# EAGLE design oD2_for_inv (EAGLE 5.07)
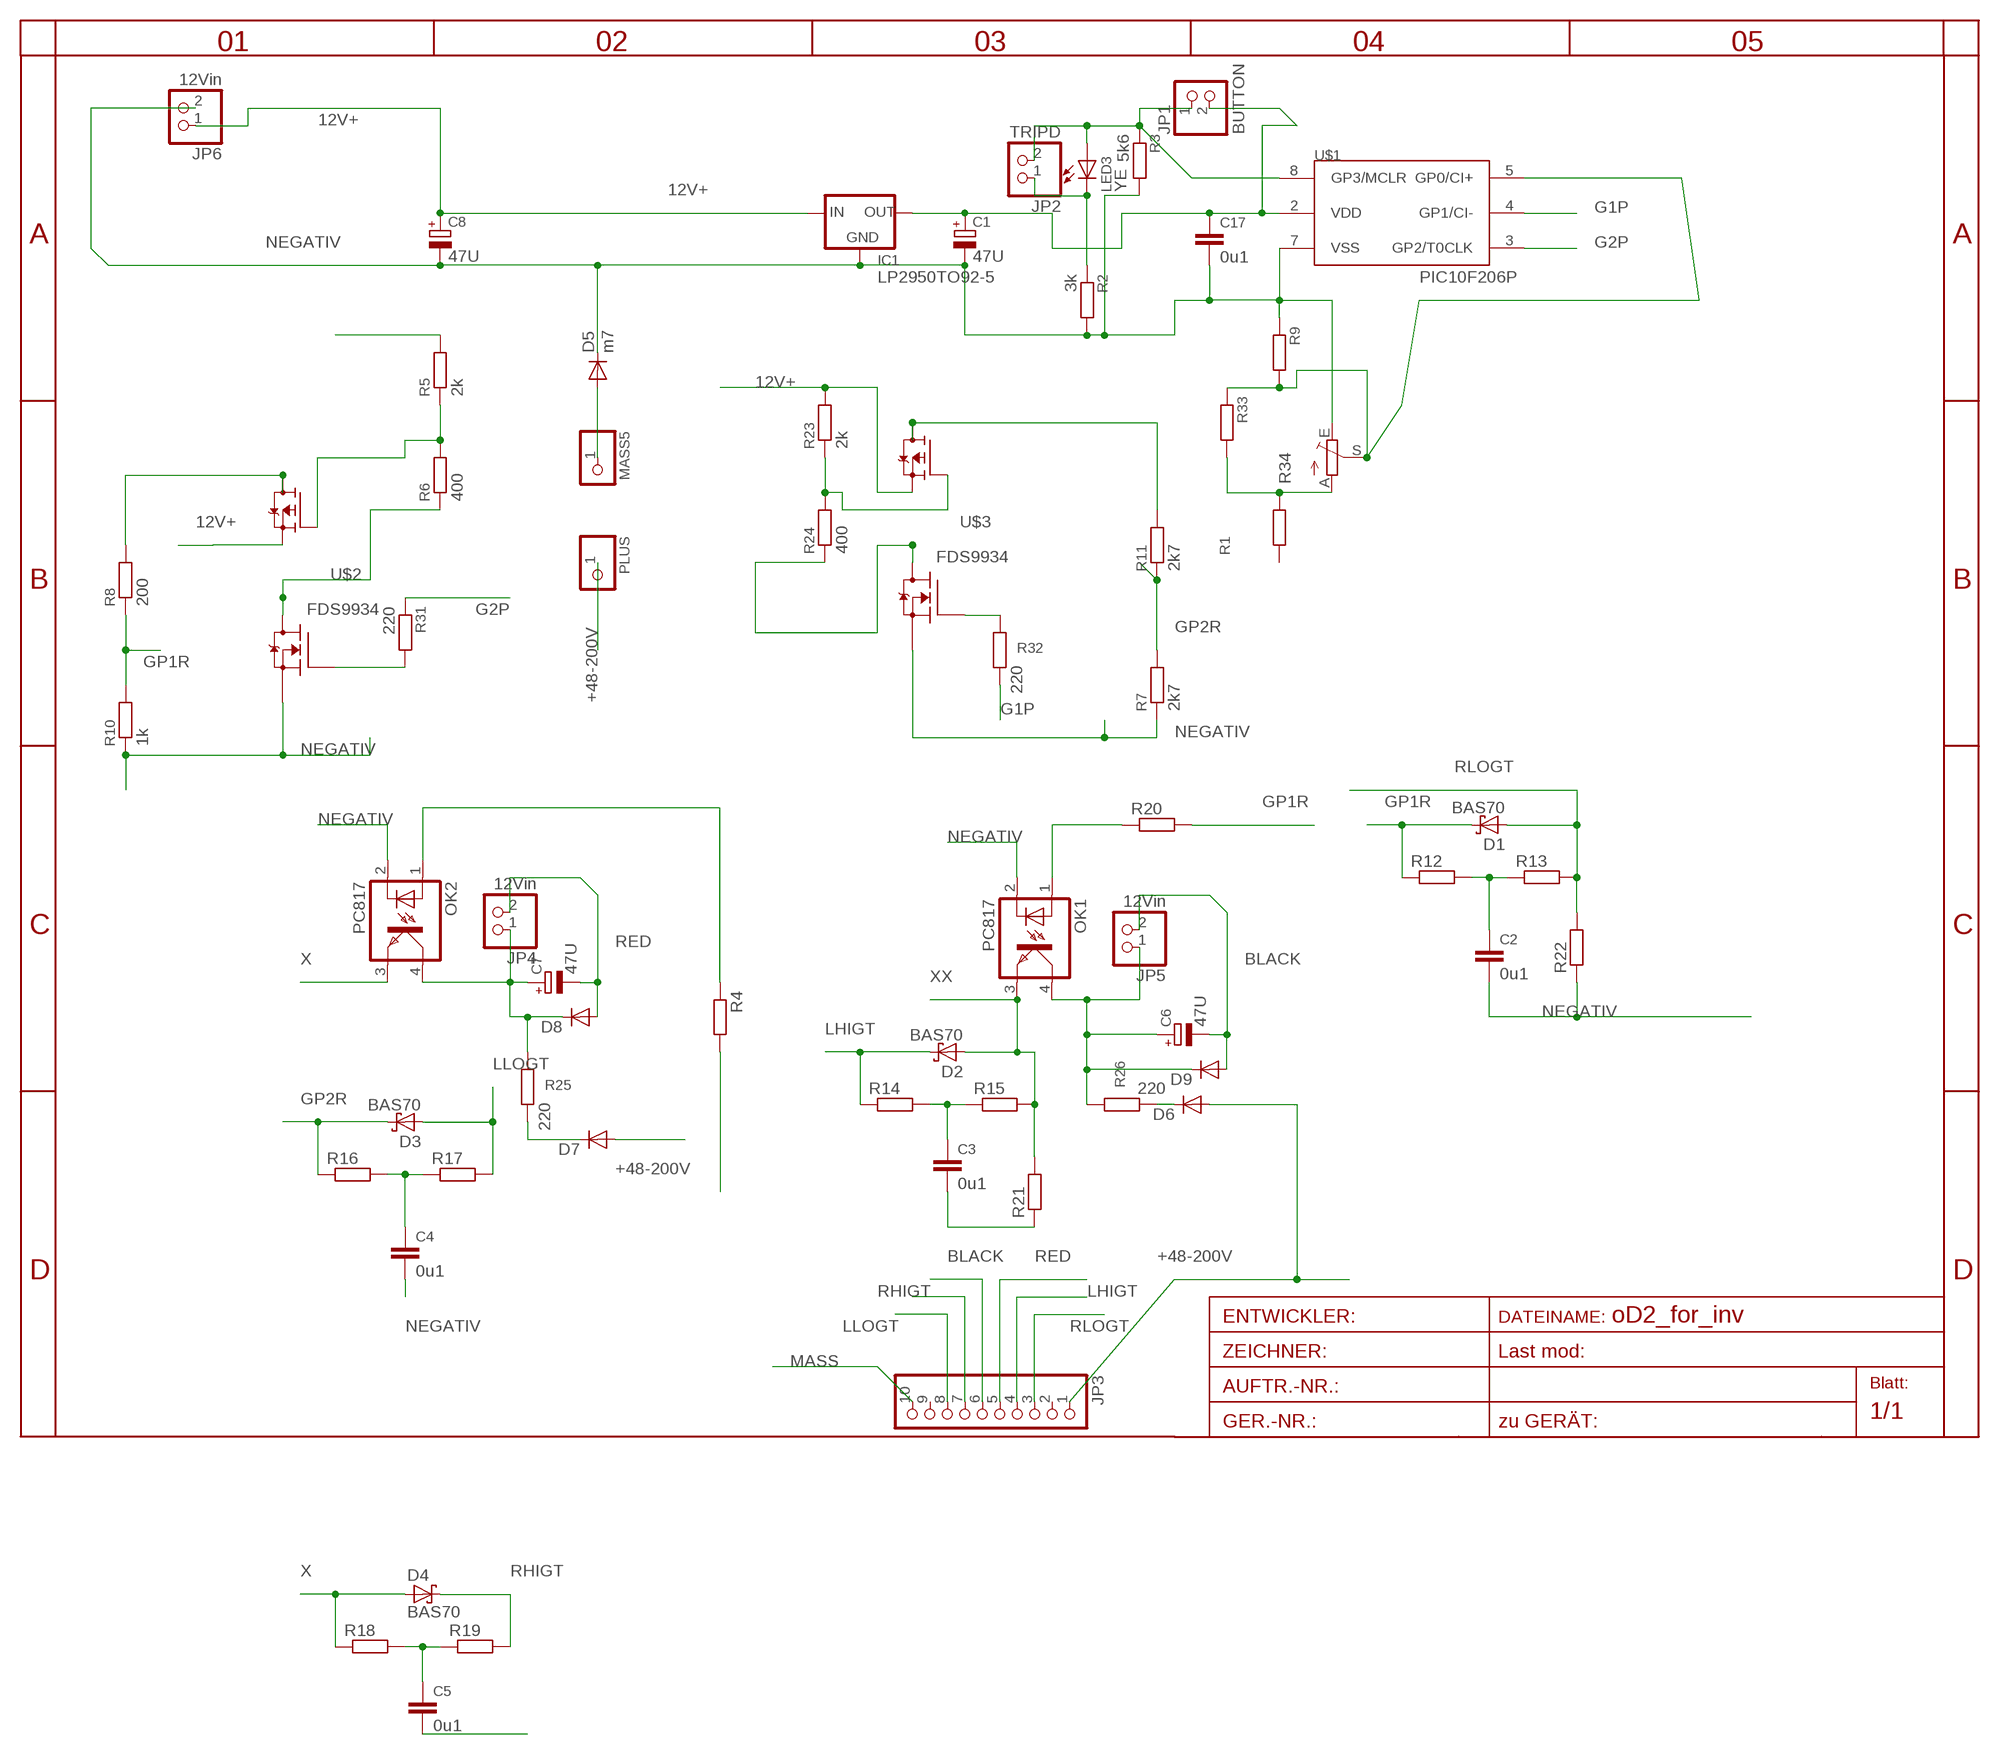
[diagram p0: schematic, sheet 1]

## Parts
C1  47U  CPOL-EUE2.5-5  [E2,5-5]
C2  0u1  C-EUC1206  [C1206]
C3  0u1  C-EUC1206  [C1206]
C4  0u1  C-EUC1206  [C1206]
C5  0u1  C-EUC1206  [C1206]
C6  47U  CPOL-EUE2.5-6  [E2,5-6]
C7  47U  CPOL-EUE2.5-6  [E2,5-6]
C8  47U  CPOL-EUE2.5-7  [E2,5-7]
C17  0u1  C-EUC1206  [C1206]
D1  BAS70  [SOT23]
D2  BAS70  [SOT23]
D3  BAS70  [SOT23]
D4  BAS70  [SOT23]
D5  m7  DIODE-SMA-DO214  [SMA-DO214AC]
D6  DIODE-D-5  [D-5]
D7  DIODE-D-5  [D-5]
D8  DIODE-MINIMELF  [MINIMELF]
D9  DIODE-MINIMELF  [MINIMELF]
IC1  LP2950TO92-5  [T092-5]
JP1  BUTTON  PINHD-1X2/90  [1X02/90]
JP2  TRIPD  PINHD-1X2/90  [1X02/90]
JP3  PINHD-1X10  [1X10WIDE]
JP4  12Vin  PINHD-1X2STR  [1X02]
JP5  12Vin  PINHD-1X2STR  [1X02]
JP6  12Vin  PINHD-1X2STR  [1X02]
LED3  YE  LEDCHIPLED_1206  [CHIPLED_1206]
MASS5  PINHD-1X11MM6  [1X1MM8]
OK1  PC817  [DIL04]
OK2  PC817  [DIL04]
PLUS  PINHD-1X11MM6  [1X1MM8]
R1  R-EU_0207/10  [0207/10]
R2  3k  R-EU_R0805  [R0805]
R3  5k6  R-EU_R0805  [R0805]
R4  R-EU_R1206  [R1206]
R5  2k  R-EU_R0805  [R0805]
R6  400  R-EU_R0805  [R0805]
R7  2k7  R-EU_R0805  [R0805]
R8  200  R-EU_R0805  [R0805]
R9  R-EU_R0805  [R0805]
R10  1k  R-EU_R0805  [R0805]
R11  2k7  R-EU_R0805  [R0805]
R12  R-EU_R0805  [R0805]
R13  R-EU_R0805  [R0805]
R14  R-EU_R0805  [R0805]
R15  R-EU_R0805  [R0805]
R16  R-EU_R0805  [R0805]
R17  R-EU_R0805  [R0805]
R18  R-EU_R0805  [R0805]
R19  R-EU_R0805  [R0805]
R20  R-EU_R0805  [R0805]
R21  R-EU_R0805  [R0805]
R22  R-EU_R0805  [R0805]
R23  2k  R-EU_R0805  [R0805]
R24  400  R-EU_R0805  [R0805]
R25  220  R-EU_R1206  [R1206]
R26  220  R-EU_R1206  [R1206]
R31  220  R-EU_R1206  [R1206]
R32  220  R-EU_R1206  [R1206]
R33  R-EU_R0805  [R0805]
R34  TRIM_EU-S64W  [S64W]
U$1  PIC10F206P  [DIL8]
U$2  FDS9934  [SO-8]
U$3  FDS9934  [SO-8]

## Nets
12V+: C8.+ IC1.3(IN) JP6.1 R5.2 R23.2 U$2.3(Q2S) U$3.3(Q2S)
+48-200V: D6.A D7.A JP3.1 PLUS.1
BLACK: C3.2 C6.- D9.A JP3.6 JP5.2 R21.1
G1P: R32.1 U$1.4(GP1/CI-)
G2P: R31.1 U$1.3(GP2/T0CLK)
GP1R: D1.3(C) R8.1 R10.2 R12.1 R20.2
GP2R: D3.3(C) R4.2 R7.2 R11.1 R16.1
GP3: JP1.1 JP2.2 LED3.A R3.1 U$1.8(GP3/MCLR)
LHIGT: D2.3(C) JP3.4 R14.1
LLOGT: D3.1(A) JP3.8 R17.2
MASS: D5.A JP3.10 MASS5.1
N$1: R9.2 R33.1 R34.S U$1.5(GP0/CI+)
N$2: R32.2 U$3.2(Q1G)
N$3: C3.1 R14.2 R15.1
N$4: R5.1 R6.2 U$2.4(Q2G)
N$5: R11.2 U$3.5(Q2D2) U$3.6(Q2D)
N$6: R31.2 U$2.2(Q1G)
N$7: C6.+ D9.C JP5.1 OK1.4(COL) R26.2
N$8: C5.1 R18.2 R19.1
N$9: R24.1 U$3.7(Q1D2) U$3.8(Q1D1)
N$11: R6.1 U$2.7(Q1D2) U$2.8(Q1D1)
N$12: C2.1 R12.2 R13.1
N$13: OK2.1(A) R4.1
N$14: C7.+ D8.C JP4.1 OK2.4(COL) R25.2
N$15: JP2.1 LED3.C R2.1
N$16: C4.1 R16.2 R17.1
N$17: OK1.1(A) R20.1
N$20: D7.C R25.1
N$21: R8.2 U$2.5(Q2D2) U$2.6(Q2D)
N$22: R23.1 R24.2 U$3.4(Q2G)
N$23: D6.C R26.1
N$42: R1.1 R33.2 R34.A
NEGATIV: C1.- C2.2 C4.2 C8.- C17.2 D5.K(C) IC1.2(GND) JP6.2 OK1.2(C) OK2.2(C) R2.2 R3.2 R7.1 R9.1 R10.1 R22.1 R34.E U$1.7(VSS) U$2.1(Q1S) U$3.1(Q1S)
RED: C5.2 C7.- D8.A JP3.5 JP4.2
RHIGT: D4.3(C) JP3.7 R19.2
RLOGT: D1.1(A) JP3.3 R13.2 R22.2
VDD: C1.+ C17.1 IC1.1(OUT) JP1.2 U$1.2(VDD)
X: D4.1(A) OK2.3(EMIT) R18.1
XX: D2.1(A) OK1.3(EMIT) R15.2 R21.2
Unconnected: JP3.2 JP3.9 R1.2

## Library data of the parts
C1 C6-C8 = rcl-2:CPOL-EU: POLARIZED CAPACITOR, European symbol
C2-C5 C17 = rcl-2:C-EU: CAPACITOR, European symbol
D1-D4 = diode:BAS70: Silicon Schottky Diodes
D5-D9 = diode:DIODE-: DIODE
IC1 = v-reg:LP2950?*: Source: http://cache.national.com/ds/LP/LP2950.pdf
JP1 JP2 JP4-JP6 = pinhead:PINHD-1X2: PIN HEADER
JP3 = pinhead:PINHD-1X10: PIN HEADER
LED3 = led:LED: LED
MASS5 PLUS = pinhead:PINHD-1X1: PIN HEADER
OK1 OK2 = optocoupler:PC817: SHARP OPTO COUPLER
R1-R3 R5-R11 R23-R26 R31-R33 = rcl-2:R-EU_: RESISTOR, European symbol
R4 R12-R22 = rcl:R-EU_: RESISTOR, European symbol
R34 = pot:TRIM_EU-: POTENTIOMETER
U$1 = microchip-5:PIC10F2*: uPC nW 0,25/0,5k Program Flash memory Comparator
U$2 U$3 = transistor-fet:FDS9934

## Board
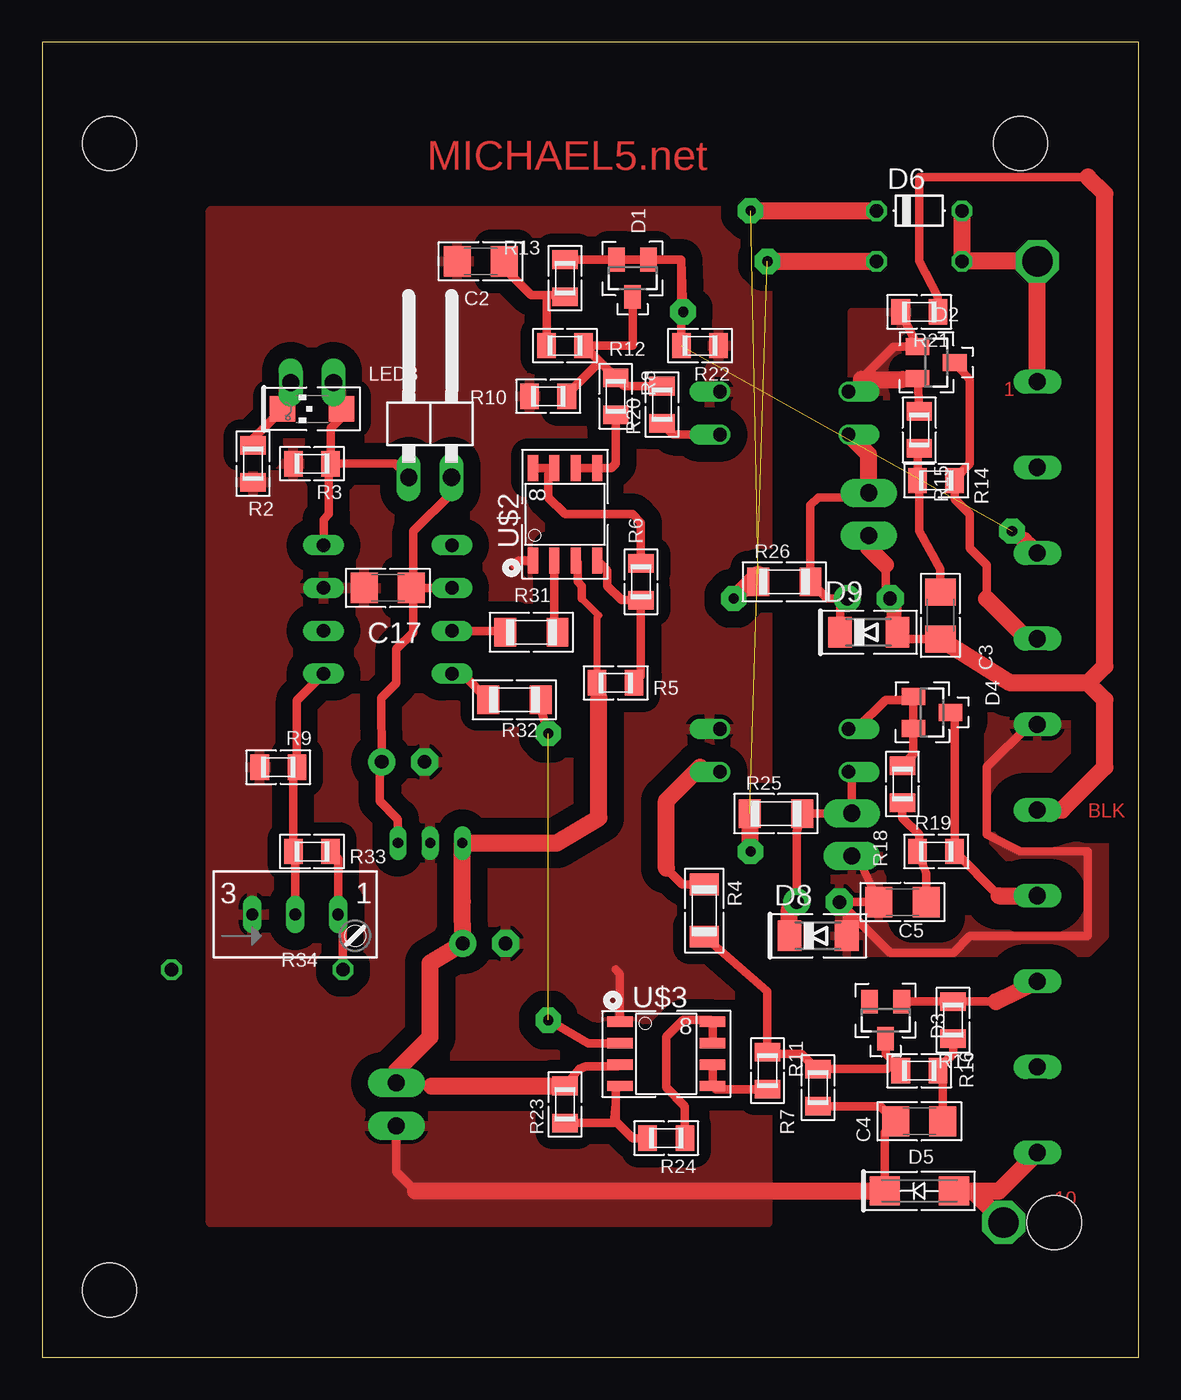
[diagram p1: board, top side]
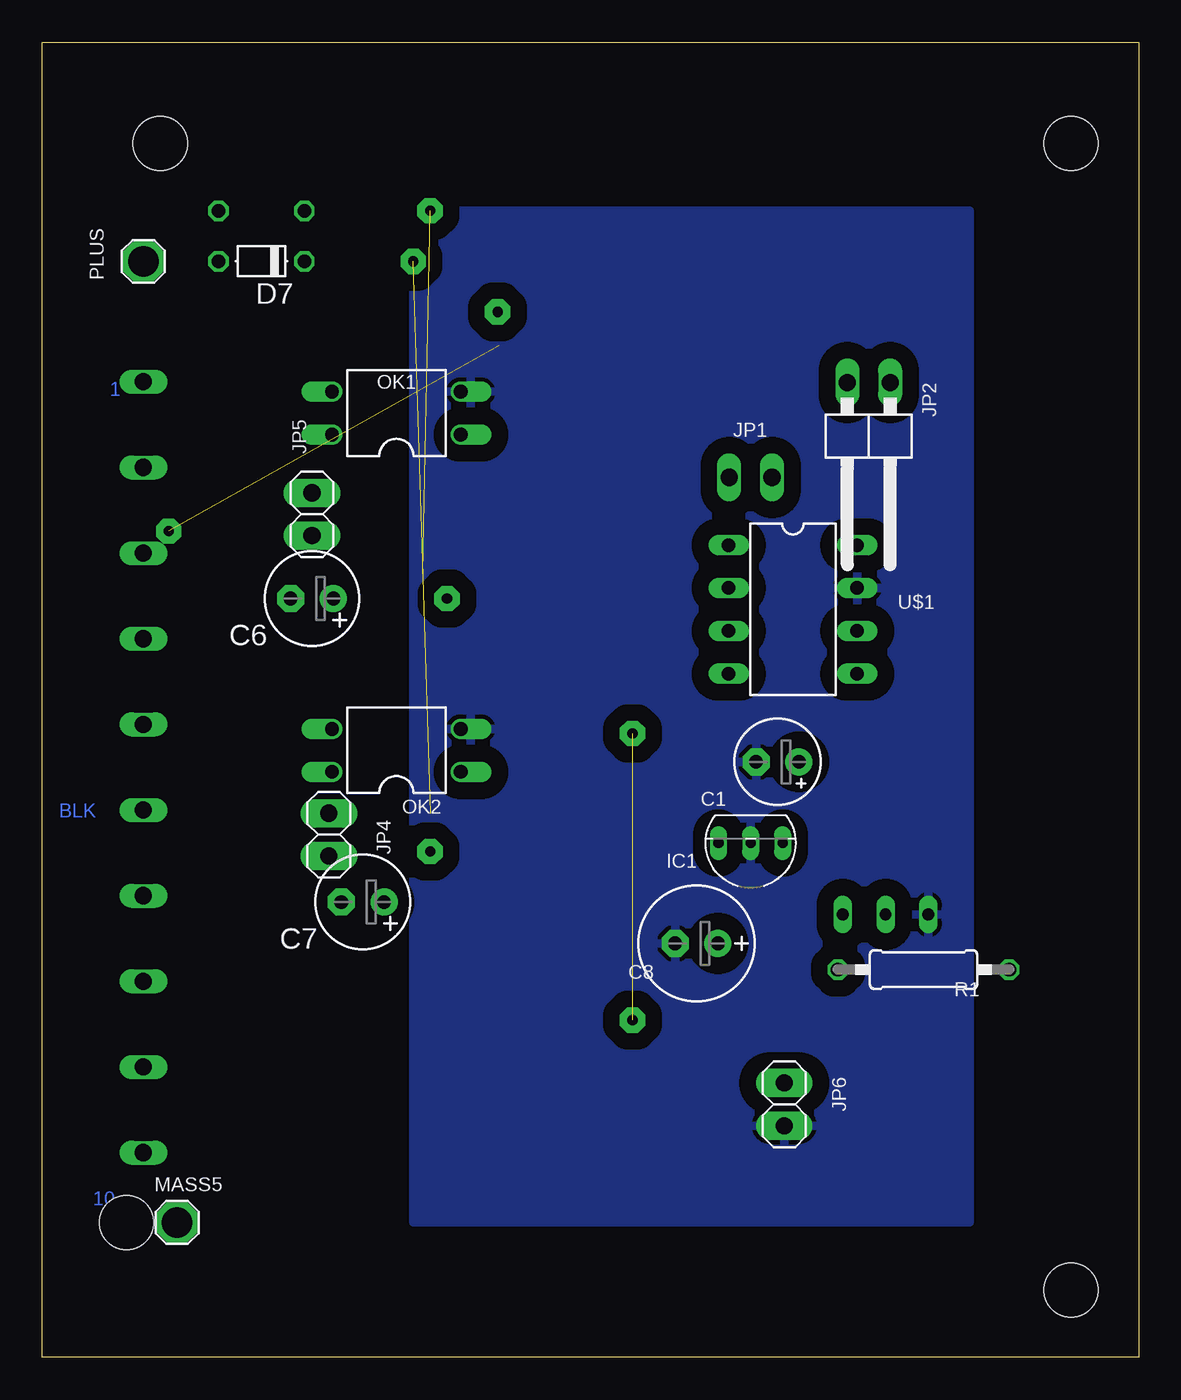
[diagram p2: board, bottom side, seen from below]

Size 65 x 78 mm. Coordinates in mm from the lower left corner, seen from the top.
Outline: 0,0 65,0 65,78 0,78 0,0
Copper layers (1*16): Top 0.035mm / dielectric 1.5mm / Bottom 0.035mm
Design rules "default *": minimum track width 12mil, minimum drill 24mil, track to track 8mil, track to pad 8mil, pad to pad 8mil, via to via 8mil, smd to smd 8mil, copper to edge 40mil, drill to drill 8mil, minimum pad ring 8mil, minimum via ring 8mil, stop-mask expansion 4mil, vias tented up to drill 0mil, thermal gap 10mil
Holes 3.2 mm at 4,72 4,4 58,72 60,8

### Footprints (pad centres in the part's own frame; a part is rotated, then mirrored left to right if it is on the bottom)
E2,5-5 = drill 0.813 pad 1.6 round: + -1.27,0 | drill 0.813 pad 1.6 octagon: - 1.27,0
C1206 = smd 1.6 x 1.8: 1 -1.4,0; 2 1.4,0
E2,5-6 = drill 0.813 pad 1.6 round: + -1.27,0 | drill 0.813 pad 1.6 octagon: - 1.27,0
E2,5-7 = drill 0.813 pad 1.6 round: + -1.27,0 | drill 0.813 pad 1.6 octagon: - 1.27,0
SOT23 = smd 1 x 1.4: 1 -0.95,-1.1; 2 0.95,-1.1; 3 0,1.1
SMA-DO214AC = smd 1.8 x 1.7: A 2.05,-0.127; K -2.05,-0.127
D-5 = drill 0.8 octagon: A 2.54,0; C -2.54,0
MINIMELF = smd 1.4 x 1.8: A 1.7,0; C -1.7,0
T092-5 = drill 0.6 pad 0.813 long: 1 -1.905,0; 2 0,0; 3 1.905,0
1X02/90 = drill 1.016 long: 1 -1.27,-3.81; 2 1.27,-3.81
1X10WIDE = drill 1.016 long: 1 -22.86,0; 2 -17.78,0; 3 -12.7,0; 4 -7.62,0; 5 -2.54,0; 6 2.54,0; 7 7.62,0; 8 12.7,0; 9 17.78,0; 10 22.86,0
1X02 = drill 1.016 pad 1.676 long: 1 -1.27,0; 2 1.27,0
CHIPLED_1206 = smd 1.5 x 1.5: A 0,-1.75; C 0,1.75
1X1MM8 = drill 1.8 pad 2.54 octagon: 1 0,0
DIL04 = drill 0.813 offset: 1 -1.27,-3.81; 2 1.27,-3.81; 3 1.27,3.81; 4 -1.27,3.81
0207/10 = drill 0.813 octagon: 1 -5.08,0; 2 5.08,0
R0805 = smd 1.1 x 1.5: 1 -1.1,0; 2 1.1,0
R1206 = smd 1.3 x 1.7: 1 -1.55,0; 2 1.55,0
S64W = drill 0.7 long: A 2.54,1.27; E -2.54,1.27; S 0,1.27
DIL8 = drill 0.8 long: 1 -3.81,-3.81; 2 -1.27,-3.81; 3 1.27,-3.81; 4 3.81,-3.81; 5 3.81,3.81; 6 1.27,3.81; 7 -1.27,3.81; 8 -3.81,3.81
SO-8 = smd 1.524 x 0.61: 1 -2.743,1.905; 2 -2.743,0.635; 3 -2.743,-0.635; 4 -2.743,-1.905; 5 2.743,-1.905; 6 2.743,-0.635; 7 2.743,0.635; 8 2.743,1.905

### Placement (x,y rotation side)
C1  21.4,35.32 180 bottom
C2  26,65 180 top
C3  53.25,44 270 top
C4  52,14 180 top
C5  51,27 180 top
C6  49,45 180 bottom
C7  46,27 180 bottom
C8  26.2,24.55 180 bottom
C17  20.49,45.63 180 top
D1  35,64 180 top
D2  53,59 270 top
D3  50,20 180 top
D4  52.75,38.25 270 top
D5  52,10 0 top
D6  52,68 0 top
D7  52,65 180 bottom
D8  46,25 0 top
D9  49,43 0 top
IC1  23,30.5 180 bottom
JP1  23,56 0 top
JP2  16,54 180 bottom
JP3  59,35 270 bottom
JP4  48,31 270 bottom
JP5  49,50 270 bottom
JP6  21,15 270 bottom
LED3  16,56.25 90 top
MASS5  57,8 0 bottom
OK1  44,56 90 bottom
OK2  44,36 90 bottom
PLUS  59,65 180 bottom
R1  12.75,23 0 bottom
R2  12.5,53 270 top
R3  16,53 180 top
R4  39.25,26.5 270 top
R5  34,40 180 top
R6  35.5,46 270 top
R7  46,16 90 top
R8  34,57 270 top
R9  14,35 0 top
R10  30,57 0 top
R11  43,17 270 top
R12  31,60 180 top
R13  31,64 90 top
R14  53,52 180 top
R15  52,55 90 top
R16  52,17 0 top
R17  54,20 90 top
R18  51,34 270 top
R19  53,30 0 top
R20  36.75,56.5 90 top
R21  52,62 180 top
R22  39,60 180 top
R23  31,15 90 top
R24  37,13 180 top
R25  43.5,32.25 0 top
R26  44,46 0 top
R31  29,43 0 top
R32  28,39 0 top
R33  16,30 0 top
R34  15,25 0 top
U$1  20.49,44.36 270 bottom
U$2  31,50 90 top
U$3  37,18 0 top

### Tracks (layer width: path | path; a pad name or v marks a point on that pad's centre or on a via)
12V+
  Top 0.406: 33,39.1 R5.2 32.9,43.9 33,44 32,45
  Top 0.5: 32,45 32,45.75 31.75,46 31.75,47.14 U$2.3 | 23.08,16.1 JP6.1 21,17 | R23.2 31.85,17.1 32.25,17.25 34.12,17.25 U$3.3
  Top 1: 33,39.1 33,32 30.5,30.5 IC1.3 24.91,27.01 C8.+ 23,23.38 23,19 21,17 | 23.08,16.1 R23.2
+48-200V
  Top 1: JP3.1 PLUS.1 D7.A D6.A
BLACK
  Top 0.5: D9.A 50.7,44.57 C6.- | 50,47 50,45.27 C6.- | C3.2 50.37,42.6 C6.- | 62,70 52,70 52,65 53.1,62.9 R21.1
  Top 1: JP3.6 60.46,32.46 63,35 63,39 62,40 | 62,40 57.4,40 C3.2 | JP5.2 49,48 50,47 | 62,70 63,69 63,41 62,40
G1P
  Top 0.5: U$1.4 24.9,40.55 R32.1
G2P
  Top 0.5: U$1.3 27.36,43.09 R31.1
GP1R
  Top 0.5: R20.2 34.5,57.6 R8.1 33.05,59.05 | 33.05,59.05 R12.1 35,60 D1.3 | R10.2 31.1,57.1 33.05,59.05
GP2R
  Top 0.5: R16.1 50.9,17.1 50.5,17.5 | 50.5,17.5 50,18 D3.3 | 50.5,17.5 50.1,17.1 R7.2 45.9,17.1 45,18 43.1,18 R11.1 43,21.7 R4.2
GP3
  Top 0.5: U$1.8 16.68,49.68 17,50 17,52.9 R3.1 | R3.1 17.1,55.1 18,56 LED3.A 17.75,57.33 JP2.2 | R3.1 20.92,53 JP1.1
LHIGT
  Top 0.5: JP3.4 58.38,42.62 | 56,45 56,47 55,48 55,50 54.1,50.9 R14.1 54.1,52.1 55,53 55,58 D2.3
  Top 1: 58.38,42.62 56,45
LLOGT
  Top 0.5: D3.1 R17.2 56.55,21.1
  Top 1: 56.55,21.1 JP3.8
MASS
  Top 0.5: D5.A 55.13,9.87
  Top 1: MASS5.1 55.13,9.87 56.73,9.87 JP3.10
N$1
  Top 0.5: R34.S 15,29.9 R33.1 14.9,34.8 R9.2 15.1,38.97 U$1.5
N$2  (via drill 0.6 pad 1.5)  (1 unrouted)
  Top 0.5: U$3.2 32.37,18.64 v30,20 | R32.2 29.55,38.45 v30,37
N$3
  Top 0.5: C3.1 53.25,46.75 52,49 52,51.9 R14.2 51.9,53.8 R15.1
N$4
  Top 0.5: R5.1 35.5,40.4 R6.2 34.35,44.9 33.5,45.75 33.5,46.66 U$2.4
N$5
  Top 0.5: R11.2 39.94,15.9 U$3.5 U$3.6
N$6
  Top 0.5: U$2.2 30.37,43.19 R31.2
N$7
  Top 0.5: D9.C 47.3,44.57 C6.+ 46.55,45 R26.2 45.55,50.55 46,51 48.73,51 JP5.1
  Top 1: JP5.1 49,53.54 OK1.4
N$8
  Top 0.5: C5.1 52.4,28.7 R19.1 52,30.1 52,31 51,32 R18.2
N$9
  Top 0.5: R24.1 38.1,14.9 37,16 37,19 38,20 39.65,20 U$3.8 U$3.7
N$11
  Top 0.5: R6.1 35.5,49.5 35,50 31,50 30,51 30,52.38 U$2.7 U$2.8
N$12
  Top 0.5: C2.1 27.4,64.6 29,63 30,63 | 30,63 30.9,63 R13.1 | R12.2 29.9,62.9 30,63
N$13
  Top 0.5: R4.1 37.95,28.05 37,29 | 39,35 39.92,35 OK2.1
  Top 1: 37,29 37,33 39,35
N$14
  Top 0.5: OK2.4 48,34.54 JP4.1 45.73,32.25 R25.2 44.73,31.18 C7.+ 44.3,26.57
  Top 1: D8.C 44.3,26.57
N$15
  Top 0.5: R2.1 12.5,54.5 LED3.C 14.25,57.33 JP2.1
N$16
  Top 0.5: C4.1 53.4,16.7 R16.2 53.1,17.1 54,18 R17.1
N$17
  Top 0.5: OK1.1 37.42,54.73 R20.1
N$20  (via drill 0.6 pad 1.5)  (1 unrouted)
  Top 1: v42,30 R25.1 | v43,65 D7.C
N$21
  Top 0.5: U$2.6 U$2.5 33.74,52.74 34,53 R8.2
N$22
  Top 0.5: R24.2 35,13 34,14 34,15 | 34,15 34,15.84 U$3.4 | R23.1 33.9,13.9 34,15
N$23  (via drill 0.6 pad 1.5)  (1 unrouted)
  Top 0.5: 42.45,46.45 R26.1
  Top 1: v41,45 42.45,46.45 | v42,68 D6.C
N$42
  Top 0.5: R1.1 17.83,25.98 R34.A 17.54,29.56 R33.2
NEGATIV
  Top 0.5: 22.13,9.87 21,11 JP6.2 | D5.K 49.95,13.35 C4.2 49.7,14.9 R7.1 | U$3.1 34.26,22.74 34,23 | U$2.1 28.26,47.26 28,47
  Top 1: 22.13,9.87 D5.K
  pour Top (isolate 1, rank 4): 10,68 43,68 43,8 10,8
  pour Bottom (isolate 1): 10,68 43,68 43,8 10,8
RED
  Top 0.5: JP4.2 48.33,29.73 C5.2 C7.- | D8.A 47.7,26.57 C7.- | JP3.5 58.54,37.54 56,35 56,31 58,30 62,30 62,25 55,25 54,24 50.27,24 C7.-
  pour Top (isolate 1.5): 55,38 61,38 61,33 63,31 63,25 62,24 47,24 47,30 50,30 50,26 59,26 59,29 55,29
RHIGT
  Top 0.5: 56.72,27.38 R19.2 54.1,38 D4.3
  Top 1: 56.72,27.38 JP3.7
RLOGT  (via drill 0.6 pad 1.5)  (1 unrouted)
  Top 0.5: 58.2,48.45 v57.5,49 | R22.2 37.9,64.9 v38,62 37.9,65.1 D1.1 R13.2
  Top 1: JP3.3 58.2,48.45
VDD
  Top 0.5: IC1.1 21.09,31.91 20,33 20,34.95 C1.+ 20.11,39.11 21,40 21,42 22,43 22,45.52 C17.1 | C17.1 U$1.2 | JP1.2 24.27,51.27 22,49 22,45.74 C17.1
X
  Top 0.5: OK2.3 48.27,37.27 50,39 51.45,39 D4.1 51.65,35.75 R18.1
XX
  Top 0.5: R15.2 51.9,58.1 51,58 | 48.58,58 OK1.3 50.49,59.95 D2.1 R21.2
  Top 1: 48.58,58 51,58
  pour Top (isolate 1.016): 51,62 48,62 48,57 52,57 52,62

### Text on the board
Top: MICHAEL5.net | 1 | BLK | 10
Bottom: 1 | BLK | 10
